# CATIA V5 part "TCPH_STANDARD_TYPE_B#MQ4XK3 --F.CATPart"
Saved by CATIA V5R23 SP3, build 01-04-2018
Part number: TCPH_STANDARD_TYPE_B#MQ4XJK
Revision: --F
Nomenclature: _
Description: TCPH_STANDARD_TYPE_B
Property "MAT": "PR"
Property "Long Description": "CRYOP_HOUSING_UPPER_POSITION_C+GS"
Property "PBS Short": "3.1"
Property "VAC & FUEL CLASS": "N"
Property "GAS CLASS": "N"
Property "WATER CLASS": "N"
Property "ELEC CLASS": "N"
Property "CODAC CLASS": "N"
Property "RH CLASS": "N"
Property "HEAT CLASS": "N"
Property "DIAG CLASS": "N"
Property "CRYO CLASS": "N"
Property "NEU CLASS": "N"
Property "ASSY CLASS": "N"
Property "SAFETY CLASS": "N"
Property "QA CLASS": "N"
Property "DEPT": "_"
Property "DIVN": "_"
Property "GROUP": "_"
Property "UNIT": "_"
Property "PARTY": "_"
Property "RO": "BHARDWA"
Property "RE": "VITUPIG"
Property "PRO": "---"
Property "Part Code": "TXT1"
Property "Part Origin": "ITER-P-3282KS+AA+-0"
Property "ITER Part Version": "-1"
Property "PBS Full Meaning": "VACUUM PUMPING"
Property "Date": "2005-11-11-09.18.13.000000"
Property "Responsible": "GLISSC"
Property "Site Resp": "SITE_AA"
Property "Organization": "ITER"
Property "Former PN": "ITER-P-3282KS"
Property "CHK MAT": "UNSYNC"
Property "PBS": "3.1 VACUUM PUMPING"
Property "Sig. Point Calc.": "N"
Property "ShortDescMig": "CRYOP_HOUSING_UPPER"
Property "PbsLevel1Mig": "31"
Property "PNMig": "235NFX"
Property "User In Enovia": "VAUQUEJ"
Property "Life Cycle Status": "Approved"
Property "ID": "MQ4XJK"
Property "AT": "PD"
Property "PBS 1": "24"
Property "PBS 2": "CR"
Property "PBS 3": "LC"
Property "LONG": "_"
Property "PREF": "Y"
Property "Change Type": "Minor"
Property "Maturity Level": "CD"
Property "Export Number": "_"
Property "REP": "CM"
Property "Object Type": "_"
Property "CADENAS_ID": "_"
Property "Description Modification": "DR-34 and DR-35"
Property "Description Documents": "_"
Property "BOM": "_"
Property "External Part ID": "ITER-C-235NEF"
Publications: "SHELL", "INTERFACE_PLATE", "VERTICAL_PLATES", "FLANGE", "INNER_CYLINDER", "POCKET", "TUBE_B1_TO_B5", "RH_POCKET", "VACUUM_PIPE"
Material "Stainless steel": density 8030 kg/m3, Young's modulus 2e+11 Pa, Poisson ratio 0.266, thermal expansion 1.17e-05 1/K
Bounding box of the stored display mesh (mm): x 13380 to 16870, y -1350 to 1350, z -6313 to -2983
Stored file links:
  C:\Users\pandeym\Desktop\__TCPH\TCPH_STANDARD_TYPE_B#MQ4XK3 --F.CATPart
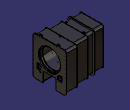
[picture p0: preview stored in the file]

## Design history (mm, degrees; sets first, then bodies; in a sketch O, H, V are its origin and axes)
Set1
  Line1 "CRYOPUMP_CENTER_AXIS": linked copy from another document
  DatumSurface1 "SURFACE_IN": linked copy from another document
  DatumSurface2 "SURFACE_OUT": linked copy from another document
  Sketch1 "TCPH_INNER_CYLINDER", origin (0, 0, 0), H (-1, 0, 0), V (0, 0, 1), geometry linked from another document
  Sketch2 "TCPH_VACUUM_PUMP_INTERFACE", origin (0, 0, 0), H (-1, 0, 0), V (0, 0, 1), geometry linked from another document
  Plane1 "CRYOPUMP_INTERFACE_PLANE_02": linked copy from another document
  Plane2 "CRYOPUMP_INTERFACE_PLANE_03": linked copy from another document
  Plane3 "CRYOPUMP_INTERFACE_PLANE_04": linked copy from another document
  Sketch3 "RH_RAIL_POCKETS", origin (15875, 0, 0), H (0, 1, 0), V (0, 0, 1), geometry linked from another document
  Sketch4 "CRYOPUMP_HOLES", origin (16720, 0, 0), H (0, 1, 0), V (0, 0, 1), geometry linked from another document
  Plane4 "CRYOPUMP_INTERFACE_PLANE_09": linked copy from another document
  Plane5 "CRYOPUMP_INTERFACE_PLANE_10": linked copy from another document
  Plane6 "CRYOPUMP_INTERFACE_PLANE_08": linked copy from another document
  Plane7 "CRYOPUMP_INTERFACE_PLANE_07": linked copy from another document
  Sketch5 "INNER_PLATES_HOLES", origin (15875, 0, 0), H (0, 1, 0), V (0, 0, 1), geometry linked from another document
  Sketch6 "TCPH_STANDARD_SHELL_03", origin (14800, 0, 0), H (0, 1, 0), V (0, 0, 1), geometry linked from another document
  Sketch7 "TCPH_FLANGE", origin (14800, 0, 0), H (0, 1, 0), V (0, 0, 1), geometry linked from another document
  Sketch8 "TCPH_STANDARD_SHELL_04", origin (13400, 0, 0), H (0, 1, 0), V (0, 0, 1), geometry linked from another document
  Sketch9 "TCPH_STANDARD_SHELL_02", origin (15855, 0, 0), H (0, 1, 0), V (0, 0, 1), geometry linked from another document
  Sketch10 "OUTER_VERTICAL_PLATES", origin (13380, 0, 0), H (0, 1, 0), V (0, 0, 1), geometry linked from another document
  Sketch11 "TCPH_TYPE_A_SHELL_01", origin (16750, 0, 0), H (0, 1, 0), V (0, 0, 1), geometry linked from another document
  Sketch12 "INTERFACE_PLATE", origin (16800, 0, 0), H (0, 1, 0), V (0, 0, 1), geometry linked from another document
  Sketch13 "SOCKET_PROFIL", origin (15540, 0, 0), H (0, 1, 0), V (0, 0, 1), geometry linked from another document
  Sketch14 "VERTICAL_PLATE_01", origin (15855, 0, 0), H (0, 1, 0), V (0, 0, 1), geometry linked from another document
  Sketch15 "VERTICAL_PLATE_02", origin (14820, 0, 0), H (0, 1, 0), V (0, 0, 1), geometry linked from another document
  DatumCurve1 "MONITORING_PIPE_PROFIL": linked copy from another document
  Sketch16 "LIFTING_PADS_HOLES", origin (0, 0, -3193), H (1, 0, 0), V (0, 1, 0), geometry linked from another document
  Sketch17 "TEMPORARY_FLANGE_HOLES", origin (16800, 0, 0), H (0, 1, 0), V (0, 0, 1), geometry linked from another document
  Sketch18 "VACUUM_PIPE_SECTION_1", origin (0, 0, -6293), H (1, 0, 0), V (0, 1, 0), geometry linked from another document
  Sketch19 "RH_RAILS_HOLES", origin (16830, 0, 0), H (0, 1, 0), V (0, 0, 1), geometry linked from another document
  Sketch20 "RH_PINS", origin (15875, 0, 0), H (0, 1, 0), V (0, 0, 1), geometry linked from another document
  Sketch21 "RH_RAILS_INTERFACE", origin (16830, 0, 0), H (0, 1, 0), V (0, 0, 1), geometry linked from another document
  Sketch22 "DIAG_TCPH_HOLES", origin (13380, 0, 0), H (0, 1, 0), V (0, 0, 1), geometry linked from another document
  Sketch23 "DIAG_TCPH_PIPES", origin (13380, 0, 0), H (0, 1, 0), V (0, 0, 1), geometry linked from another document
  Sketch24 "FLANGE_DOCKING_PINS", origin (16800, 0, 0), H (0, 1, 0), V (0, 0, 1), geometry linked from another document
  Sketch25 "VERTICAL_PLATE_05", origin (14820, 0, 0), H (0, 1, 0), V (0, 0, 1), geometry linked from another document
Set2 "CONST"
  Extract1: ExtractElem face of Pad14
  Extract2: ExtractElem end face of Pad14
  Extract3: ExtractElem face of Pad14
  Extract4: ExtractElem face of Pad14
  Join1: Elements (Extract4; Extract3; Extract2; Extract1)
Body1 "SHELL" (main body)
  Pad1: profile Sketch9, direction (1, 0, 0), up to start face of Pad9, opposite side up to Plane3
  Pad2: profile Sketch6, direction (1, 0, 0), up to face of Solid1, opposite side up to Plane6
  Pad3: profile Sketch11, direction (1, 0, 0), up to Plane2
  Body2 "FLANGE"
    Solid1: linked copy from another document
  Remove1: tool Body2
  Split1: SplitPlane Join1
  Pad4: profile Sketch8, direction (1, 0, 0), up to DatumSurface1
  Sketch26 on face of Pad1, origin (0, 0, -6213), H (1, 0, 0), V (0, -1, 0)
    projected circle E1 centre (15565, 780) radius 77.04 from edge of Sketch18
  Pocket1: profile Sketch26, direction (0, 0, 1), length 70
Body3 "INTERFACE_PLATE"
  Pad5: profile Sketch12, direction (1, 0, 0), up to Plane1
  Shaft1: profile Sketch2, axis axis of face of Shaft2, angle 360
  Pad6: profile Sketch24, direction (1, 0, 0), length 70
  Chamfer1: length 20, angle 30, on edge [face of Pad6 | end face of Pad6]; end face of Pad6
  Sketch27 on face of Shaft1, origin (16800, -579.3117, -3160), H (0, 1, 0), V (0, 0, 1)
    point P1 (579.3117, -3)
    reference projected point E1 (579.3117, -3) from vertex of Sketch17
    coincidence: P1 E1
  Hole1: placed by Sketch27, at (16800, 0, -3163) direction (-1, 0, 0), diameter 22, through (limit type 3)
  UserPattern1: of Hole1, copies 49, at the points of Sketch17
  Sketch28 on face of Shaft1, origin (16720, -88.6401, -3549.6454), H (0, 1, 0), V (0, 0, 1)
    point P1 (-759.3599, -843.3546)
    reference projected point E1 (-759.3599, -843.3546) from vertex of Sketch4
    coincidence: E1 P1
  Hole2: placed by Sketch28, at (16720, -848, -4393) direction (-1, 0, 0), diameter 20.752, depth 80, V-bottom angle 120, threaded "M24", thread diameter 24, thread depth 70, pitch 3
  UserPattern2: of Hole2, copies 61, at the points of Sketch4
  Pocket2: profile Sketch22, direction (-1, 0, 0), up to face of Shaft1
  Pad7: profile Sketch21, direction (1, 0, 0), up to face of Shaft1
  Sketch29 on start face of Pad7, origin (16830, -750, -5093), H (0, 1, 0), V (0, 0, 1)
    point P1 (-50, 0)
    reference projected point E1 (-50, 0) from vertex of Sketch19
    coincidence: E1 P1
  Hole3: placed by Sketch29, at (16830, -800, -5093) direction (-1, 0, 0), diameter 13.835, up to face of Shaft1, threaded "M16", thread diameter 16, thread depth 30, pitch 2
  UserPattern3: of Hole3, copies 14, at the points of Sketch19
Body4 "VERTICAL_PLATES"
  Pad8: profile Sketch14, direction (1, 0, 0), up to Plane3, opposite side up to Plane2
  Pad9: profile Sketch15, direction (1, 0, 0), up to Plane6, opposite side up to Plane7
  Pad10: profile Sketch10, direction (1, 0, 0), up to Plane5, opposite side up to Plane4
  Pocket3: profile Sketch5, direction (-1, 0, 0), up to start face of Pad10
  Split2: SplitPlane Join1
  Pocket4: profile Sketch22, direction (-1, 0, 0), through (limit type 3)
  Sketch30 on start face of Pad16, origin (15825, 0, 0), H (0, 1, 0), V (0, 0, 1)
    projected line E1 (-736.7157, -5093) -> (-970, -5093) from edge of Sketch3
    projected line E2 (-970, -5468) -> (-645, -5468) from edge of Sketch3
    projected line E3 (-645, -5468) -> (-645, -5184.7157) from edge of Sketch3
    projected line E4 (-645, -5184.7157) -> (-736.7157, -5093) from edge of Sketch3
    projected line E5 (-970, -5093) -> (-970, -5468) from edge of Sketch3
    projected line E6 (645, -5184.7157) -> (645, -5468) from edge of Sketch3
    projected line E7 (736.7157, -5093) -> (645, -5184.7157) from edge of Sketch3
    projected line E8 (970, -5093) -> (736.7157, -5093) from edge of Sketch3
    projected line E9 (970, -5468) -> (970, -5093) from edge of Sketch3
    projected line E10 (645, -5468) -> (970, -5468) from edge of Sketch3
  Pocket5: profile Sketch30, direction (-1, 0, 0), up to start face of Pad8
  Thickness1: Face (face of Pocket4; face of Pocket4; face of Pocket4), Thickness -15.45
  Thickness2: Face (face of Pocket4; face of Pocket4), Thickness -12.85
Body5 "FLANGE"
  Pad11: profile Sketch7, direction (1, 0, 0), up to DatumSurface1, opposite side up to DatumSurface2
  Pocket6: profile Sketch5, direction (-1, 0, 0), through (limit type 6)
  Sketch31 "DIAG_TCPH_HOLES", origin (13380, 0, 0), H (0, 1, 0), V (0, 0, 1), geometry linked from another document
  Pocket7: profile Sketch31, direction (-1, 0, 0), through (limit type 3)
  Sketch32 on end face of Pad10, origin (13380, 0, 0), H (0, -1, 0), V (0, 0, 1)
    circle A1 centre (-990, -3363) radius 2
    point P1 (-990, -3363)
    construction line L1 (-990, -3363.1789) -> (-990, -3371.8598)
    point P4 (-990, -3363.1789)
    point P5 (-990, -3371.8598)
    axis line L2 (-1063.4425, -3363) -> (-1052.2485, -3363)
    point P6 (-1063.4425, -3363)
    point P7 (-1052.2485, -3363)
    reference projected point E2 (-990, -3363) from vertex of DatumCurve1
    reference projected point E3 (-990, -3363) from vertex of DatumCurve1
    reference intersected line E4 through (0, 0) direction (0, -1) from zx-plane
    point P11 (990, -3371.8598)
    point P12 (990, -3363.1789)
    construction line L3 (990, -3363.1789) -> (990, -3371.8598)
    point P13 (1052.2485, -3363)
    point P14 (1063.4425, -3363)
    construction line L4 (1063.4425, -3363) -> (1052.2485, -3363)
    circle A2 centre (990, -3363) radius 2
    radius A1 = 2
    distance P1 L2 = 0
    vertical: L1 V
    horizontal: L2 H
    coincidence: L2 E2, L1 E3, P1 L1
    symmetry: P5 P11 E4, P4 P12 E4, L1 L3 E4, P7 P13 E4, P6 P14 E4, L2 L4 E4, A1 A2 E4
  Pocket8: profile Sketch32, direction (1, 0, 0), through (limit type 3)
  Sketch33 on end face of Pad10, origin (13380, 0, 0), H (0, -1, 0), V (0, 0, 1)
    projected circle E1 centre (-990, -3363) radius 2 from edge [face of Pocket8 from Sketch32.A1 | end face of Pad11]
    circle A1 centre (-990, -3363) radius 3
    point P1 (-990, -3363)
    reference intersected line E4 through (0, 0) direction (0, -1) from zx-plane
    circle A2 centre (990, -3363) radius 3
    circle A3 centre (990, -3363) radius 2
    distance A1 E1 = 1
    concentricity: P1 E1
    symmetry: E1 A3 E4, A1 A2 E4
  Pad12: profile Sketch33, direction (1, 0, 0), length 885, opposite side length -765
  Thickness3: Face (face of Pocket7; face of Pocket7; face of Pocket7), Thickness -15.45
  Thickness4: Face face of Pocket7, Thickness -12.85
Body6 "INNER_CYLINDER"
  Shaft2: profile Sketch1, axis Line1, angle 360
Body7 "POCKET"
  Pad13: profile Sketch13, direction (1, 0, 0), up to end face of Pad5
  Sketch34 on start face of Pad13, origin (15540, 0, 0), H (0, -1, 0), V (0, 0, 1)
    projected line E1 (615, -5343) -> (615, -6253) from edge [start face of Pad13 | face of Pad13]
    projected line E2 (-615, -6253) -> (-615, -5343) from edge [start face of Pad13 | face of Pad13]
    projected line E3 (-615, -5343) -> (615, -5343) from edge [start face of Pad13 | face of Pad13]
    line L1 (-615, -6253) -> (615, -6253)
    horizontal: L1 H
  Pad14: profile Sketch34, direction (-1, 0, 0), length 20
  Pocket9: profile Sketch22, direction (-1, 0, 0), up to start face of Pad14
Body8 "TUBE_B1_TO_B5"
  Pad15: profile Sketch23, direction (-1, 0, 0), up to face of Shaft1
  Sketch35 on face of Shaft1, origin (16800, 0, 0), H (0, -1, 0), V (0, 0, 1)
    line L1 (-549.7423, -5417.269) -> (541.682, -5417.269)
    line L2 (541.682, -5417.269) -> (541.682, -5843.7993)
    line L3 (541.682, -5843.7993) -> (-549.7423, -5843.7993)
    line L4 (-549.7423, -5843.7993) -> (-549.7423, -5417.269)
    horizontal: L1 H, L3 H
    vertical: L2 V, L4 V
  Pocket10: profile Sketch35, direction (1, 0, 0), up to start face of Pad13, offset -245
Body9 "RH_POCKET"
  Pad16: profile Sketch3, direction (1, 0, 0), up to end face of Pad5, opposite side length 50
  Pad17: profile Sketch30, direction (-1, 0, 0), length 20
  Body10 "POCKET"
    Solid2: linked copy from another document
  Remove2: tool Body10
  Pad18: profile Sketch20, direction (1, 0, 0), up to start face of Pad17
  Chamfer2: length 20, angle 30, on edge [face of Pad18 | start face of Pad18] (x2)
Body11 "VACUUM_PIPE"
  Pad19: profile Sketch18, direction (0, 0, 1), length 80
Body12 "LIFTING_PADS"
  Sketch36 "LIFTING_PADS", origin (0, 0, -3193), H (1, 0, 0), V (0, 1, 0), geometry linked from another document
  Pad20: profile Sketch36, direction (0, 0, 1), length 60
  Sketch37 on end face of Pad20, origin (15830, 0, -3133), H (1, 0, 0), V (0, 1, 0)
    point P1 (100, 0)
    reference projected point E1 (100, 0) from vertex of Sketch16
    coincidence: P1 E1
  Hole4: placed by Sketch37, at (15930, 0, -3133) direction (0, 0, -1), diameter 31.67, through (limit type 3), threaded "M36", thread diameter 36, thread depth 60, pitch 4
  UserPattern4: of Hole4, copies 3, at the points of Sketch16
